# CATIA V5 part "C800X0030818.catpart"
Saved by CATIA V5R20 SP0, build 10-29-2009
Part number: C800X0030818
Source: Unknown
Property "A": "30"
Property "ARTICLENO": "C800X0030818"
Property "B": "13"
Property "BOMINFO": "C800X0030818"
Property "C": "46"
Property "CA": "C800X0030818"
Property "D1": "38"
Property "DES": "ROTATING EYEBOLT WITH RING Ton 0,3 M8x18"
Property "E": "50"
Property "H": "105"
Property "L": "18"
Property "LINA": "C800X0030818"
Property "NB": "C800X0030818"
Property "NBSYN": "$CODE."
Property "NN": "C800X"
Property "NT": "Rotating eyebolt with ring"
Property "SIZE": "M8"
Property "SUPPLIER": "CF"
Property "SW": "30"
Property "WEIGHT": "480"
Property "WLL": "0.30"
Bounding box of the stored display mesh (mm): x -27.983 to 27.983, y -18 to 117.837, z -19 to 19
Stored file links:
  C:\Users\Utente\Desktop\3D files 800X\C800X0030818.catpart

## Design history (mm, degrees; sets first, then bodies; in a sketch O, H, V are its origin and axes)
Body1 "Geometry.1" (main body)
  Solid1 "C800X0030818.catpart": solid without history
